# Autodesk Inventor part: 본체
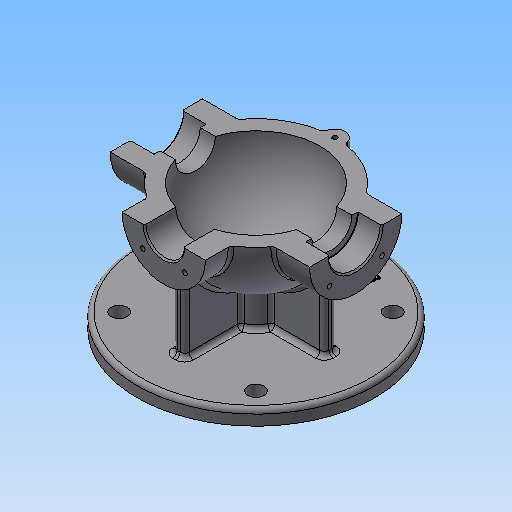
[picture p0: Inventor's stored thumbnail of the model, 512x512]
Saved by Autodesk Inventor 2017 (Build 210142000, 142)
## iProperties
Created: 2015-12
Part Number: 본체
Material: 일반
Document SubType Name: Modeling
Designer: mduedu
Density: 2.71 g/cm^3
Appearance: 기본값
Author: mduedu
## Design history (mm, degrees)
sketch "스케치1"
  geometry: L1 (-53, 0)-(53, 0); A1 r 53 centre (0, 0) between (53, 0) and (-53, 0); 2 further points
  constraints: 2 coincident, 2 end point, 2 point on circle, 1 centre point, 1 horizontal, 1 midpoint
  dimensions: "d0" = 53 radius of A1
revolve "회전1" sketch "스케치1" stored, may be unused: angle "d2" = 90 deg
feature "쉘1" dims "d11" = 10
node "작업 평면1"
sketch "스케치2"
  geometry: C1 r 31 at (0, 0); 1 further point
  constraints: 1 centre point, 1 coincident
  dimensions: "d4" = 62 diameter of C1
extrude "돌출1" join sketch "스케치2" stored distance "d5" = 10; taper "d6" = 0 deg
node "작업 평면2"
sketch "스케치3"
  geometry: C1 r 28 at (0, 0); 1 further point
  constraints: 1 centre point, 1 coincident
  dimensions: "d8" = 56 diameter of C1
extrude "돌출2" join sketch "스케치3" stored distance "d9" = 10; taper "d10" = 0 deg
hole "구멍1" diameter "d14" = 35; stored, may be unused: countersink angle "d18" = 90 deg, drill point angle "d20" = 0 deg; dims "d12" = 10, "d13" = 10, "d15" = 6, "d16" = 4, "d17" = 2, "d19" = 16
hole "구멍2" diameter "d23" = 27; stored, may be unused: countersink angle "d27" = 90 deg, drill point angle "d29" = 0 deg; dims "d21" = 10, "d22" = 10, "d24" = 6, "d25" = 4, "d26" = 2, "d28" = 16
fillet "모깎기1" dims "d30" = 0.3
hole "구멍3" diameter "d33" = 26; stored, may be unused: countersink angle "d37" = 90 deg, drill point angle "d39" = 0 deg; dims "d31" = 10, "d32" = 10, "d34" = 6, "d35" = 4, "d36" = 2, "d38" = 16
chamfer "모따기1" distance "d40" = 1; stored, may be unused: second distance "d41" = 2, angle "d42" = 45 deg
sketch "스케치4"
  geometry: L1 (0, 0)-(0, -25); L2 (0, 0)-(-17.678, -17.678); A1 r 25 centre (0, 0) between (-17.678, -17.678) and (0, -25); 1 further point
  constraints: 4 end point, 2 point on circle, 1 centre point, 1 coincident, 1 vertical
  dimensions: "d43" = 50 diameter of A1; "d47" = 45 deg angle of L1 L2
hole "구멍4" sketch "스케치4" at (-17.678, -17.678) diameter "d49" = 3.242; stored, may be unused: countersink angle "d53" = 90 deg, drill point angle "d55" = 118 deg; dims "d50" = 11, "d51" = 4, "d52" = 2, "d54" = 13
sketch "스케치5"
  geometry: L1 (0, 0)-(0, -20); L2 (0, 0)-(-14.142, -14.142); A1 r 20 centre (0, 0) between (0, -20) and (-14.142, -14.142); 2 further points
  constraints: 4 end point, 2 coincident, 2 point on circle, 1 centre point, 1 vertical
  dimensions: "d59" = 40 diameter of A1; "d65" = 45 deg angle of L1 L2
hole "구멍5" sketch "스케치5" at (-14.142, -14.142) diameter "d67" = 3.242; stored, may be unused: countersink angle "d71" = 90 deg, drill point angle "d73" = 118 deg; dims "d68" = 8, "d69" = 4, "d70" = 2, "d72" = 10
node "작업 평면3"
sketch "스케치6"
  geometry: C1 r 80 at (0, 0); 1 further point
  constraints: 1 centre point, 1 coincident
  dimensions: "d78" = 160 diameter of C1
extrude "돌출3" join sketch "스케치6" distance "d80" = 10; taper "d81" = 0 deg
sketch "스케치7"
  geometry: C1 r 15 at (0, 0); 1 further point
  constraints: 1 centre point, 1 coincident
  dimensions: "d82" = 30 diameter of C1
extrude "돌출4" join sketch "스케치7" stored distance "d84" = 10; taper "d85" = 0 deg
sketch "스케치8"
  geometry: 2 further points
  constraints: 1 coincident
hole "구멍6" sketch "스케치8" at (0, 0) diameter "d86" = 20; stored, may be unused: countersink angle "d90" = 90 deg, drill point angle "d92" = 118 deg; dims "d87" = 7, "d88" = 100, "d89" = 5, "d91" = 10
fillet "모깎기2" dims "d93" = 0.3
sketch "스케치9"
  geometry: L1 (-67, -18.5)-(-66, -17.5) reference; L2 (-66, -17.5)-(-51.3, -17.5) reference; L3 (-51, -17.2)-(-51, -13.5) reference; L4 (-51, -13.5)-(-40.826, -13.5) reference; L5 (-10, -41.821)-(-10, -80) reference; L6 (-10, -80)-(-49.7, -80) reference; L7 (-50, -80.3)-(-50, -85) reference; L8 (-50, -85)-(-80, -85) reference; L9 (-80, -85)-(-80, -75) reference; L10 (-80, -75)-(-15, -75) reference; L11 (-15, -75)-(-15, -50.833) reference; L12 (-42.988, -31)-(-67, -31) reference; L13 (-67, -31)-(-67, -18.5) reference; L14 (66, -17.5)-(67, -18.5) reference; L15 (67, -18.5)-(67, -31) reference; L16 (67, -31)-(42.988, -31) reference; L17 (15, -50.833)-(15, -75) reference; L18 (15, -75)-(80, -75) reference; L19 (80, -75)-(80, -85) reference; L20 (80, -85)-(50, -85) reference; L21 (50, -85)-(50, -80.3) reference; L22 (49.7, -80)-(10, -80) reference; L23 (10, -80)-(10, -41.821) reference; L24 (40.826, -13.5)-(51, -13.5) reference; L25 (51, -13.5)-(51, -17.2) reference; L26 (51.3, -17.5)-(66, -17.5) reference; L27 (67, 18.5)-(66, 17.5) reference; L28 (66, 17.5)-(51.3, 17.5) reference; L29 (51, 17.2)-(51, 13.5) reference; L30 (51, 13.5)-(40.826, 13.5) reference; L31 (-40.826, 13.5)-(-51, 13.5) reference; L32 (-51, 13.5)-(-51, 17.2) reference; L33 (-51.3, 17.5)-(-66, 17.5) reference; L34 (-66, 17.5)-(-67, 18.5) reference; L35 (-67, 18.5)-(-67, 31) reference; L36 (-67, 31)-(-42.988, 31) reference; L37 (42.988, 31)-(67, 31) reference; L38 (67, 31)-(67, 18.5) reference; L39 (-50, -31)-(-50, -75); A1 r 0.3 centre (-51.3, -17.2) between (-51.3, -17.5) and (-51, -17.2) reference; A2 r 43 centre (0, 0) between (-40.826, -13.5) and (-10, -41.821) reference; A3 r 0.3 centre (-49.7, -80.3) between (-49.7, -80) and (-50, -80.3) reference; A4 r 53 centre (0, 0) between (-42.988, -31) and (-15, -50.833) reference; A5 r 53 centre (0, 0) between (15, -50.833) and (42.988, -31) reference; A6 r 0.3 centre (49.7, -80.3) between (50, -80.3) and (49.7, -80) reference; A7 r 43 centre (0, 0) between (10, -41.821) and (40.826, -13.5) reference; A8 r 0.3 centre (51.3, -17.2) between (51, -17.2) and (51.3, -17.5) reference; A9 r 0.3 centre (51.3, 17.2) between (51.3, 17.5) and (51, 17.2) reference; A10 r 43 centre (0, 0) between (40.826, 13.5) and (-40.826, 13.5) reference; A11 r 0.3 centre (-51.3, 17.2) between (-51, 17.2) and (-51.3, 17.5) reference; A12 r 53 centre (0, 0) between (42.988, 31) and (-42.988, 31) reference; 1 further point
  constraints: 2 end point, 2 point on line
  dimensions: "d173" = 30 distance from line of L39.end L9; "d174" = 90 deg angle of L10 L39
feature "리브1" sketch "스케치9" dims "d96" = 1, "d97" = 8, "d98" = 0, "d99" = 0, "d100" = 1, "d101" = 1
sketch "스케치14"
  geometry: L1 (-14, 62)-(-13, 61) reference; L2 (-13, 61)-(-13, 40.988) reference; L3 (-41.821, 10)-(-80, 10) reference; L4 (-80, 10)-(-80, 49.7) reference; L5 (-80.3, 50)-(-85, 50) reference; L6 (-85, 50)-(-85, 80) reference; L7 (-85, 80)-(-75, 80) reference; L8 (-75, 80)-(-75, 15) reference; L9 (-75, 15)-(-50.833, 15) reference; L10 (-28, 45)-(-28, 62) reference; L11 (-28, 62)-(-14, 62) reference; L12 (13, 61)-(14, 62) reference; L13 (14, 62)-(28, 62) reference; L14 (28, 62)-(28, 45) reference; L15 (-50.833, -15)-(-75, -15) reference; L16 (-75, -15)-(-75, -80) reference; L17 (-75, -80)-(-85, -80) reference; L18 (-85, -80)-(-85, -50) reference; L19 (-85, -50)-(-80.3, -50) reference; L20 (-80, -49.7)-(-80, -10) reference; L21 (-80, -10)-(-41.821, -10) reference; L22 (13, 40.988)-(13, 61) reference; L23 (-28, 52)-(-75, 52); A1 r 43 centre (0, 0) between (-13, 40.988) and (-41.821, 10) reference; A2 r 0.3 centre (-80.3, 49.7) between (-80, 49.7) and (-80.3, 50) reference; A3 r 53 centre (0, 0) between (-28, 45) and (-50.833, 15) reference; A4 r 53 centre (0, 0) between (0, -53) and (28, 45) reference; A5 r 53 centre (0, 0) between (-50.833, -15) and (0, -53) reference; A6 r 0.3 centre (-80.3, -49.7) between (-80.3, -50) and (-80, -49.7) reference; A7 r 43 centre (0, 0) between (-41.821, -10) and (0, -43) reference; A8 r 43 centre (0, 0) between (0, -43) and (13, 40.988) reference; 1 further point
  constraints: 2 end point, 2 point on line
  dimensions: "d175" = 28 distance of L7.end L23.end; "d176" = 90 deg angle of L8 L23
feature "리브2" sketch "스케치14" dims "d153" = 1, "d154" = 8, "d155" = 0, "d156" = 0, "d157" = 1, "d158" = 1
sketch "스케치10"
  geometry: L1 (0, 0)-(0, -65); L2 (0, 0)-(-45.962, -45.962); A1 r 65 centre (0, 0) between (0, -65) and (-45.962, -45.962); 2 further points
  constraints: 4 end point, 2 coincident, 2 point on circle, 1 centre point, 1 vertical
  dimensions: "d105" = 130 diameter of A1; "d107" = 45 deg angle of L1 L2
hole "구멍7" sketch "스케치10" at (-45.962, -45.962) diameter "d109" = 11; stored, may be unused: countersink angle "d113" = 90 deg, drill point angle "d115" = 118 deg; dims "d110" = 7, "d111" = 18, "d112" = 4, "d114" = 10
fillet "모깎기3" dims "d120" = 3
fillet "모깎기4" dims "d121" = 3, "d122" = 3
fillet "모깎기5" dims "d123" = 3
fillet "모깎기6" dims "d124" = 3
sketch "스케치11"
  geometry: C1 r 80 at (0, 0) reference; C2 r 65 at (0, 0)
  constraints: 1 centre point, 1 coincident, 1 other
  dimensions: "d161" = 130 diameter of C2
feature "엠보싱1" sketch "스케치11" dims "d11" = 10, "d125" = 0.5, "d126" = 0
sketch "스케치12"
  geometry: L1 (0, 100)-(0, -100); L2 (0, 100)-(100, 100); L3 (100, 100)-(100, -100); L4 (100, -100)-(0, -100); 2 further points
  constraints: 8 end point, 3 perpendicular, 1 coincident, 1 midpoint, 1 vertical
  dimensions: "d127" = 200 distance of L2.end L3.end; "d129" = 100 distance between parallel lines of L1 L3
extrude "돌출5" cut sketch "스케치12" stored distance "d130" = 10; taper "d131" = 0 deg
sketch "스케치13"
  geometry: C1 r 7 at (0, 53); A1 r 53 centre (0, 0) between (42.113, 32.179) and (-42.113, 32.179) reference; 1 further point
  constraints: 1 centre point, 1 point on circle
  dimensions: "d132" = 14 diameter of C1
extrude "돌출6" join sketch "스케치13" distance "d134" = 15; taper "d135" = 0 deg
hole "구멍8" diameter "d139" = 3.242; stored, may be unused: countersink angle "d143" = 90 deg, drill point angle "d145" = 118 deg; dims "d140" = 8, "d141" = 4, "d142" = 2, "d144" = 10, "d148" = 10, "d149" = 10
fillet "모깎기7" dims "d146" = 3
fillet "모깎기8" dims "d147" = 3
node "솔리드1"
mirror "대칭1"
mirror "대칭2"
pattern_circular "원형 패턴1" dims angle "d57" = 360 deg
mirror "대칭3"
pattern_circular "원형 패턴2" dims angle "d75" = 360 deg
mirror "대칭4"
pattern_circular "원형 패턴4" dims angle "d118" = 360 deg
node "절단 모서리 투영1"
node "절단 모서리 투영2"
other parameters: "d3" = 67, "d7" = 62, "d77" = -85
